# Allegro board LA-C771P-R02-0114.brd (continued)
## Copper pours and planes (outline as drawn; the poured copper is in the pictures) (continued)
+3VALW_EC on TOP (solid shape): 63.48,30.99 63.79,30.81 64.09,30.99 69.22,30.99 69.35,30.87 69.35,30.84 69.51,30.68 69.51,30.2 69.75,29.96 69.75,29.93 69.77,29.78 69.84,29.65 69.84,28.34 69.84,28.34 69.84,26.99 69.79,26.93 69.65,26.93 69.63,26.95 69.63,28.96 69.37,29.22 65.44,29.22 65.03,28.81 65.03,26.27 64.83,26.07 62.16,26.07 62.16,26.08 61.96,26.08 61.83,26.12 61.7,26.13 61.67,26.12 61.45,26.34 61.45,27.22 61.46,27.27 61.46,27.31 61.46,28.04 61.46,28.08 61.45,28.13 61.45,29.9 62.54,30.99
+3VALW_EC on TOP (solid shape): outline of 89 points within 53.02,1.31 81.59,32.55
+3VALW_EC on BOTTOM (solid shape): outline of 145 points within 53.37,28.61 63.91,33.61
+3VALWP on BOTTOM (solid shape): 204.3,40.19 204.3,35.54 201.89,33.13 200.14,33.13 199.96,33.31 199.96,34.27 199.65,34.58 199.16,34.58 197.61,36.13 197.61,39.94 196.81,40.75 196.81,42.09 197.06,42.35 202.14,42.35
+3VDD_CODEC on TOP (solid shape): 31.29,30.32 31.28,30.3 31.28,29.41 31.35,29.41 31.35,29.3 31.04,28.99 29.34,28.99 28.93,28.99 27.95,28 27.95,27.29 27.69,27.03 26.94,27.03 26.86,27.12 26.86,28.05 28.41,29.6 28.41,29.88 28.56,30.03 28.56,30.2 28.63,30.28 30.05,30.28 30.21,30.44 31.17,30.44
+3VLP on BOTTOM (solid shape): 189.44,42.12 189.44,41.57 189.68,41.33 189.87,41.33 190.59,40.61 190.59,39.96 190.53,39.9 190.37,39.9 190.34,39.94 190.34,40.48 190.06,40.76 189.42,40.76 189.01,41.18 187.99,41.18 187.86,41.31 187.86,42.25 187.94,42.32 189.24,42.32
+3VS on TOP (solid shape): 76.13,5.85 76.13,5.39 75.88,5.14 75.39,5.14 74.91,4.66 73.69,4.66 73.21,5.14 73.21,5.88 73.36,6.03 75.95,6.03
+3VS on TOP (solid shape): 79,76.18 79,75.39 78.97,75.37 78.97,74.78 78.8,74.6 77.98,74.6 77.86,74.73 77.86,76.15 77.96,76.26 78.92,76.26
+3VS on TOP (solid shape): 76.81,89.61 76.82,89.54 76.82,88.6 77.31,88.11 77.32,88.1 77.64,87.57 78.02,87.09 78.04,87.08 78.04,85.86 77.86,85.68 77.05,85.68 76.79,85.94 76.79,85.96 76.69,86.19 76.46,86.29 76.44,86.29 76.18,86.55 75.37,86.55 74.96,86.14 74.89,86.14 74.81,86.06 74.23,86.06 73.9,86.39 73.9,86.85 74.26,87.22 74.44,87.22 74.56,87.33 74.56,88.42 74.6,88.43 74.91,88.71 74.75,89.09 74.75,89.68 74.89,89.82 76.59,89.82
+3VS on TOP (solid shape): 177.02,86.85 177.02,86.14 177.01,86.13 177.01,85.39 176.82,85.2 173.31,85.2 172.79,85.72 172.76,85.82 172.84,85.9 173.07,86.4 172.54,86.52 172.43,86.51 172.37,86.6 172.37,86.84 172.52,87.13 172.37,87.42 172.37,87.89 172.63,88.15 175.72,88.15
+3VS on TOP (solid shape): outline of 501 points within 117.89,1.38 210.78,40.75
+3VS on TOP (solid shape): outline of 1002 points within 28.65,9.67 76.41,100.44
+3VS on BOTTOM (solid shape): 62.16,100.9 62.16,98.2 62.2,98.16 62.2,98.05 62,97.85 60.51,97.85 60.15,98.21 60.15,98.52 60.98,99.34 61,99.35 61.23,99.5 61.33,99.77 61.33,100.66 61.32,100.72 61.6,101 62.06,101
+3VS on IN1 (solid shape): 185.25,22.16 186.82,22.16 187.15,21.83 187.15,20.18 186.47,19.49 183.14,19.49 182.05,20.58 182.05,22.79 182.51,23.25 184.16,23.25
+3VS on IN1 (solid shape): 179.03,86.78 179.03,85.84 178.98,85.78 178.98,84.41 178.62,84.06 175.34,84.06 175.19,84.21 175.19,86.93 175.45,87.18 178.62,87.18
+3VS on IN2 (solid shape): outline of 619 points within 38.82,1.53 126.6,11.08
+3VS_CMOS on BOTTOM (solid shape): 55.35,94.87 55.35,92.72 55.76,92.31 56.55,92.31 56.72,92.13 56.72,91.27 56.57,91.11 54.46,91.11 54.31,91.27 54.31,94.98 54.36,95.03 55.2,95.03
+3VS_OUT on TOP (solid shape): 186.47,24.72 186.7,24.64 186.92,24.72 187.89,24.72 187.93,24.68 187.93,24.02 187.94,24.02 187.94,21.93 187.86,21.85 187.18,21.85 187.15,21.82 187.15,21.32 187.13,21.29 186.77,21.29 186.75,21.32 186.75,21.82 186.72,21.85 185.98,21.85 185.96,21.82 185.96,21.32 185.93,21.29 185.55,21.29 185.53,21.32 185.53,21.8 185.5,21.82 184.87,21.82 184.82,21.87 184.82,23.37 185.15,23.7 185.15,24.24 185.22,24.31 185.88,24.31 186.29,24.72
+3VS_TCM on TOP (solid shape): 93.71,20.3 93.71,19.18 93.48,18.95 90.43,18.95 90.38,19 90.38,19.46 90.51,19.59 90.51,20.45 90.56,20.5 93.5,20.5
+3VS_TCM on TOP (solid shape): 101.25,26.66 101.25,21.7 101.25,21.67 101.02,21.45 100.92,21.34 100.92,18.8 100.29,18.17 99.42,18.17 99.07,18.53 99.07,19.41 99.6,19.95 99.6,21.57 100.06,22.03 100.06,22.06 100.06,22.07 100.11,22.25 100.06,22.43 100.06,24.11 100.06,24.12 100.08,24.24 100.06,24.36 100.06,24.37 100.06,25.13 99.3,25.89 97.8,25.89 97.67,26.02 97.67,26.3 97.77,26.4 99.5,26.4 99.96,26.86 101.05,26.86
+3VS_TCM on BOTTOM (solid shape): 101,19.39 101,18.45 100.9,18.35 91.68,18.35 91.04,18.98 91.04,19.54 91.17,19.67 100.72,19.67
+3VS_WLAN on TOP (solid shape): 173.96,94.05 173.94,94.02 173.85,93.48 174.05,92.96 174.05,88.81 172.56,88.81 172.56,88.53 172.12,88.53 171.35,89.29 171.35,89.46 171.4,89.5 171.4,92.38 172.19,93.17 172.19,94.06 172.63,94.5 173.52,94.5
+3VS_WLAN on BOTTOM (solid shape): 154.87,92.8 154.87,90.74 154.08,89.95 153.17,89.95 153.02,90.1 153.02,90.38 153.4,90.76 153.4,92.8 153.53,92.92 154.74,92.92
+3VS_WLAN on IN1 (solid shape): 160.92,94.45 160.92,93.72 160.92,93.65 160.94,93.58 160.94,93.4 161.25,93.1 167.27,93.1 167.34,93.07 167.37,93 167.77,92.67 168.07,93.1 168.09,93.19 168.17,93.23 171.61,93.23 171.61,93.23 171.96,93.23 172.21,93.48 172.21,94.38 172.27,94.45 173.43,94.45 173.8,94.07 173.8,89.47 173.32,89 171.72,89 170.78,89.94 170.67,89.94 170.47,90.14 170.04,90.14 169.82,90.36 169.82,90.39 169.82,90.45 169.81,90.52 169.52,90.83 169.14,90.65 169.1,90.66 169.08,90.68 168.84,90.78 168.6,90.7 168.54,90.67 168.48,90.69 168.22,90.78 167.97,90.65 167.91,90.59 154.45,90.59 153.72,89.86 152.64,89.86 151.94,90.56 149.09,90.56 148.24,91.41 148.24,92.94 148.43,93.34 148.44,93.77 148.43,93.8 148.47,93.84 148.47,94.29 148.65,94.47 149.54,94.47 149.72,94.29 149.72,93.94 149.64,93.86 149.64,93.61 150.15,93.1 159.67,93.1 159.85,93.28 159.9,93.28 159.98,93.35 160.06,93.42 160.12,93.49 160.21,93.58 160.21,94.45 160.26,94.5 160.87,94.5
+5V_HUB on TOP (solid shape): 193.96,57.26 194.52,57.26 194.67,57.11 194.67,55.84 194.47,55.63 194.47,53.09 194.46,53.08 194.46,52.78 194.34,52.66 193.17,52.66 192.96,52.88 192.96,56.69 193.56,57.29 193.94,57.29
+5V_ODD on TOP (solid shape): 225.31,109.45 225.86,109.07 226.41,109.45 226.42,109.48 226.51,109.48 226.87,109.12 226.87,107.28 226.54,106.94 225.46,106.94 225.41,106.89 225.37,106.93 225.37,106.94 224.33,106.9 224.96,106.07 225.04,106.05 225.08,105.97 225.08,105.17 224.79,104.88 221.52,104.88 221.44,104.96 221.44,105.72 221.93,106.22 221.93,107.35 224.06,109.48 225.3,109.48
+5VALW on TOP (solid shape): 192.13,30.01 192.13,28.38 192.06,28.3 191.55,28.3 191.34,28.1 191.34,27.56 189.85,26.07 189.24,26.07 189.13,26.17 189.13,26.73 188.76,27.11 188.76,29.3 189.77,30.31 191.83,30.31
+5VALW on TOP (solid shape): 191.14,54.62 191.85,54.62 191.96,54.52 191.96,54.14 192.13,53.96 192.67,53.96 192.77,53.86 192.77,52.43 192.23,51.9 190.08,51.9 189.9,52.08 189.9,52.13 189.75,52.28 188.98,52.28 188.73,52.54 188.73,53.86 188.83,53.96 189.09,53.96 189.75,54.62 190.33,54.62 190.48,54.77 190.99,54.77
+5VALW on BOTTOM (solid shape): 36.74,49.74 36.74,37.37 40.37,33.73 41.95,33.73 41.96,33.74 43.52,33.74 43.57,33.69 43.57,33.23 43.59,33.21 45.55,33.21 45.58,33.23 45.58,33.69 45.63,33.74 47.4,33.74 47.41,33.74 47.55,33.74 47.68,33.61 47.68,31.35 47.61,31.27 39.07,31.27 33.6,36.75 33.6,36.84 32.8,37.64 32.8,39.66 32.7,39.66 32.06,40.29 17.94,40.29 17.48,40.75 17.48,42.27 17.58,42.38 18.7,42.38 19.06,42.02 22,42.02 23.43,43.44 28.86,43.44 35.57,50.15 36.33,50.15
+5VALW on IN1 (solid shape): outline of 115 points within 182.94,27.31 193.12,54.77
+5VALW on IN1 (solid shape): outline of 2550 points within 40.72,5.11 181.66,33.99
+5VALW on IN2 (solid shape): outline of 1216 points within 173.31,8.52 195,30.18
+5VALWP on BOTTOM (solid shape): 48.98,41.03 48.98,37.08 48.96,37.06 48.96,35.34 47.53,33.91 41.92,33.91 39.68,36.15 39.68,37.72 39.83,37.87 41.32,37.87 41.51,38.06 41.51,38.88 43.11,40.47 46.21,40.47 47.02,41.28 48.72,41.28
+5VS on TOP (solid shape): 225.17,103.73 225.17,100.84 224.81,100.49 223.14,100.49 222.6,101.03 222.6,101.75 221.3,103.05 221.3,104.01 221.43,104.15 224.76,104.15
+5VS on TOP (solid shape): 33.57,25.85 34.08,25.85 35.24,24.7 35.24,14.46 36.36,13.34 36.36,13.24 36.71,12.89 36.71,11.52 36.25,11.06 35.62,11.06 33.89,12.79 33.89,23.58 32.72,24.75 31.5,24.75 31.43,24.82 31.43,25.76 31.53,25.87 33.56,25.87
+5VS on TOP (solid shape): 18.18,15.41 18.18,15.23 18.18,15.23 18.08,14.35 18.18,13.47 18.18,13.47 18.18,12.87 17.97,12.66 17.2,12.66 17,12.86 17,15.5 17.08,15.58 18.02,15.58
+5VS on TOP (solid shape): 21.01,89.77 21.01,88.65 20.86,88.5 16.87,88.5 16.66,88.71 16.66,88.74 16.64,88.95 16.49,89.11 16.49,89.67 16.76,89.94 18.28,89.94 18.34,90 18.42,90.03 18.49,89.99 18.83,89.88 19.09,90.12 19.1,90.15 20.63,90.15
+5VS on TOP (solid shape): outline of 202 points within 180.12,29.24 210.42,52.1
+5VS on BOTTOM (solid shape): outline of 571 points within 180.35,5.62 194.85,32.09
+5VS on IN1 (solid shape): 22.08,89.85 22.08,88.71 21.72,88.35 20.2,88.35 19.74,88.81 19.74,89.72 20.28,90.26 21.67,90.26
+5VS on IN1 (solid shape): 225.21,103.4 225.21,98.65 225.01,98.46 222.91,98.46 222.62,98.74 222.62,102.98 223.4,103.76 224.84,103.76
+5VS on IN1 (solid shape): 188.12,30.74 188.12,29.3 188.11,29.28 188.11,28.77 187.82,28.48 182.94,28.48 181.95,29.47 181.95,32.24 182.38,32.67 186.19,32.67
+5VS on IN1 (solid shape): outline of 372 points within 103.21,1.3 193.06,10.7
+5VS on IN1 (solid shape): outline of 1094 points within 17.1,1.41 79.69,15.76
+5VS_HDD on TOP (solid shape): 211,55.08 211.69,55.08 211.75,55.01 212.29,55.01 212.4,54.89 212.4,51.59 212.27,51.47 211.13,51.47 210.22,52.38 207.81,52.38 207.68,52.51 207.68,54.54 207.92,54.78 207.92,55.11 207.93,55.13 207.93,55.86 208.14,56.07 210.01,56.07
+5VS_OUT on TOP (solid shape): 188.27,29.06 188.27,27.16 187.86,26.75 187.86,26.09 187.84,26.07 186.77,26.07 186.24,26.6 185.45,26.6 185.45,26.6 185.22,26.6 185.15,26.68 185.15,29.04 185.22,29.11 188.22,29.11
+5VS_PVDD on TOP (solid shape): 30.97,27.18 30.97,25.68 30.9,25.68 30.9,24.79 30.92,24.79 30.96,24.76 30.95,24.7 30.89,24.65 30.11,24.65 30.03,24.72 30.03,24.97 30.03,24.97 30.03,25.59 30.03,25.68 29.83,25.89 28.94,25.89 28.81,26.01 28.81,27.16 29.09,27.44 30.71,27.44
+5VS_PVDD on BOTTOM (solid shape): 30,27.64 30,27.01 29.75,26.75 29.24,26.75 29.22,26.78 29.06,26.78 28.56,26.27 27.84,26.27 27.84,28.22 27.88,28.25 27.92,28.28 29.37,28.28
+12.6VB_DDR on TOP (solid shape): 142.95,31.41 142.95,28.77 143.13,28.59 143.13,26.3 143.32,26.11 143.32,26.04 143.19,25.92 143.13,25.92 142.94,26.11 141.99,26.11 141.86,26.23 141.86,26.61 141.61,26.87 140.91,26.87 140.46,27.31 140.46,31.25 140.78,31.57 142.8,31.57
+12.6VB_DDR on BOTTOM (solid shape): 143,28.77 143,26.3 142.81,26.11 141.99,26.11 141.99,26.61 141.73,26.87 139.75,26.87 139.51,27.11 139.51,28.14 139.57,28.2 140.78,28.2 141.16,28.58 141.16,28.77 141.29,28.9 142.88,28.9
+AV12 on TOP (solid shape): 45.73,15.2 45.78,15.13 45.91,15.02 45.91,14.61 45.86,14.57 43.93,14.57 43.54,14.18 43.54,13.98 43.47,13.9 42.93,13.9 42.83,14 42.83,15.83 42.88,15.88 45.04,15.88
+V18R on TOP (solid shape): 83.11,26.17 83.11,25.43 82.96,25.28 82.12,25.28 81.4,24.55 81.22,24.55 81.11,24.45 81.11,24.44 78.9,24.44 78.85,24.49 78.85,24.62 78.92,24.69 80.73,24.69 80.76,24.72 80.78,24.72 81.7,25.64 81.75,25.72 81.77,25.82 81.77,25.84 82.28,26.34 82.94,26.34
+VCC_LPC on TOP (solid shape): 75.88,31 76.1,31 76.19,30.9 76.19,30.23 76.2,30.16 76.23,30.08 76.23,29.92 75.22,28.91 74.84,28.91 73.74,30.01 73.74,30.87 73.87,31 75.88,31
+VCC_SPI on TOP (solid shape): 82.9,28.93 82.9,26.58 82.84,26.52 82.04,26.52 81.69,26.17 81.69,25.94 81.62,25.86 81.62,25.81 81.49,25.69 81.24,25.69 81.24,28.72 81.48,28.97 82.87,28.97
GND on TOP (solid shape): 28.94,44.03 28.94,40.32 26.98,38.36 25.05,38.36 24.26,39.15 24.26,44.18 24.32,44.23 28.74,44.23
GND on TOP (solid shape): 34.75,63.43 34.75,61.5 34.55,61.3 33.26,61.3 32.57,61.98 32.57,63.43 32.77,63.63 34.56,63.63
GND on TOP (solid shape): 65.43,74.49 65.43,72.96 65.24,72.77 64.45,72.77 63.74,73.48 63.74,74.13 64.29,74.68 65.24,74.68
GND on TOP (solid shape): 92.34,92.57 92.34,89.37 92.16,89.19 89.75,89.19 89.7,89.24 89.7,92.82 89.75,92.87 92.03,92.87
GND on TOP (solid shape): 147.12,65.82 147.12,62.16 146.75,61.8 143.92,61.8 143.74,61.98 143.74,65.79 143.91,65.96 146.98,65.96
GND on TOP (solid shape): 157.3,63.33 157.3,60.63 157.07,60.4 154.57,60.4 154.36,60.62 154.36,63.3 154.58,63.52 157.12,63.52
GND on TOP (solid shape): 199.11,69.1 199.11,68.27 198.98,68.14 197.2,68.14 197.07,68.27 197.07,69.1 197.2,69.22 198.98,69.22
GND on TOP (solid shape): 199.12,79.69 199.12,78.42 198.99,78.29 197.59,78.29 197.54,78.34 197.54,79.61 197.72,79.79 199.02,79.79
GND on TOP (solid shape): 60.94,64.17 60.94,63.12 60.84,63.02 59.49,63.02 59.26,62.79 56.24,62.79 55.96,63.07 55.96,64.22 56.09,64.34 60.76,64.34
GND on TOP (solid shape): 37.19,70.03 37.19,68.72 36.74,68.26 36.74,67.67 35.88,66.81 34.68,66.81 34.07,67.41 34.07,69.68 34.88,70.49 36.74,70.49
GND on TOP (solid shape): 68.24,72.33 68.24,70.71 68.23,70.69 66.49,70.69 66.13,71.06 66.13,71.44 66.19,71.5 66.57,71.5 67.08,72.01 67.08,72.33 67.14,72.39 68.18,72.39
GND on TOP (solid shape): 154.61,32.27 154.88,32.27 154.94,32.2 154.94,30.8 154.88,30.74 152.76,30.74 152.48,31.02 152.48,32.26 152.58,32.36 154.52,32.36
GND on TOP (solid shape): 70.81,83.41 70.85,83.41 71.54,82.72 71.54,80.18 71.43,80.07 69.63,80.07 69.36,80.33 69.36,83.33 69.53,83.5 70.72,83.5
GND on TOP (solid shape): 111.82,97.98 111.82,95.18 111.81,95.17 111.81,94.76 111.72,94.67 107.7,94.67 107.63,94.75 107.63,95.79 107.7,95.87 107.7,96.17 108.06,96.53 108.06,97.98 108.24,98.15 111.64,98.15
GND on TOP (solid shape): 141.36,71.28 141.36,69.02 141.08,68.74 140.37,68.74 139.63,69.48 135.8,69.48 135.36,69.05 135.01,69.05 134.53,69.53 134.53,70.62 134.73,70.82 139.66,70.82 140.34,71.51 141.13,71.51
GND on TOP (solid shape): 166.18,73.08 166.18,69.05 165.84,68.72 153.9,68.72 153.65,68.97 153.65,72.42 154.08,72.85 157.49,72.85 158.19,72.14 161.15,72.14 161.63,72.63 161.63,73.41 161.88,73.67 165.59,73.67
GND on TOP (solid shape): 59.62,61.57 59.62,59.85 59.57,59.8 58.98,59.8 58.86,59.92 58.86,60.41 58.8,60.47 58.8,60.53 58.74,60.53 58.71,60.56 58.15,60.56 57.97,60.74 57.97,61.65 58.05,61.73 59.47,61.73
GND on TOP (solid shape): 201.39,72.08 203.23,72.08 203.23,71.45 202.79,71.45 202.53,71.19 202.53,69.99 202.22,69.67 199.55,69.67 199.36,69.86 199.36,71.7 199.49,71.83 200.06,71.83 200.19,71.95 200.19,72.46 200.25,72.53 200.95,72.53
GND on TOP (solid shape): 44.61,98.59 44.61,96.91 43.14,95.44 40.72,95.44 39.89,94.6 39.88,94.6 39.56,94.27 33.77,94.27 33.62,94.42 33.62,97.26 34.04,97.68 36.12,97.68 36.22,97.79 36.33,97.79 37.39,98.84 44.36,98.84
GND on TOP (solid shape): 86.8,84.03 86.8,83.42 86.49,83.12 85.55,83.12 85.38,82.94 85.38,81.67 85.3,81.59 84.34,81.59 84.18,81.75 84.18,83.14 84.26,83.22 84.79,83.22 84.89,83.32 84.89,83.32 85.83,84.26 86.57,84.26
GND on TOP (solid shape): 192.83,56.33 192.83,54.25 192.72,54.14 192.23,54.14 192.08,54.29 192.08,54.57 192.08,54.67 191.93,54.82 191.27,54.82 191.07,55.03 191.07,55.59 191.23,55.75 191.23,55.88 191.78,56.42 192.21,56.42 192.74,56.42
GND on TOP (solid shape): 209.41,47.94 209.41,47.3 209.35,47.25 208.69,47.25 208.67,47.23 208.49,47.23 208.16,46.9 208.16,41.77 207.81,41.41 206.47,41.41 206,41.88 206,47.48 206.54,48.01 209.33,48.01
GND on TOP (solid shape): 147.13,28.77 147.13,27.95 147.32,27.76 147.89,27.76 148.08,27.57 149.54,27.57 149.61,27.5 149.61,26.49 149.23,26.11 143.7,26.11 143.64,26.17 143.64,27.83 143.97,28.16 144.74,28.16 145.48,28.9 147,28.9
GND on TOP (solid shape): 143.3,86.62 143.3,83.5 142.14,82.35 139.43,82.35 137.98,80.91 133.64,80.91 133.51,81.03 133.51,82.11 133.7,82.3 136.16,82.3 136.18,82.33 136.31,82.33 136.96,82.99 138.11,82.99 138.69,83.57 138.69,84.41 139.48,85.2 139.81,85.2 141.61,87 142.91,87
GND on TOP (solid shape): 147.95,79.27 147.95,74.85 147.6,74.5 134.2,74.5 133.76,74.94 133.76,75.77 134.17,76.18 138.36,76.18 138.99,75.54 142.93,75.54 142.94,75.56 144.16,75.56 145.07,76.47 145.07,79.22 145.23,79.38 147.83,79.38
GND on TOP (solid shape): 185.26,66.68 190.47,66.68 190.62,66.53 190.62,65.57 190.77,65.41 192.12,65.41 192.31,65.6 192.31,66.37 192.5,66.56 193.33,66.56 193.33,65.22 192.88,64.78 185.45,64.78 184.37,65.86 184.37,66.81 184.44,66.87 185.07,66.87
GND on TOP (solid shape): 63.35,61.63 63.35,60.84 63.46,60.74 63.99,60.74 64.06,60.66 64.06,59.85 63.86,59.64 62.64,59.64 62.24,59.24 61.83,59.24 61.78,59.29 61.78,60.15 61.63,60.3 60.41,60.3 60.36,60.36 60.36,61.22 60.38,61.24 62.26,61.24 62.31,61.3 62.31,61.57 62.46,61.73 63.25,61.73
GND on TOP (solid shape): 95.66,95.87 95.66,94.62 95.59,94.55 94.72,94.55 94.47,94.8 94.47,95.26 94.29,95.44 94.29,95.51 94.22,95.51 94.19,95.54 94.17,95.55 93.88,95.64 93.58,95.54 93.56,95.54 93.48,95.61 93.48,96.4 93.78,96.71 94.83,96.71
GND on TOP (solid shape): 113.83,74.86 113.83,73.92 114.23,73.51 114.23,72.9 114.12,72.79 114.12,71.55 114.15,71.51 114.15,70.8 114.08,70.72 113.47,70.72 113.42,70.77 113.42,71.56 113.35,71.64 113.35,72.68 113.06,72.97 112.77,72.97 112.58,73.16 112.58,73.41 112.66,73.49 112.94,73.49 112.96,73.52 112.99,73.52 112.99,73.54 113.06,73.62 113.06,74.13 112.99,74.2 112.99,74.28 112.91,74.28 112.83,74.35 112.56,74.35 112.48,74.43 112.48,74.94 112.58,75.04 113.65,75.04
GND on TOP (solid shape): 111.86,78.77 112.43,78.77 112.44,78.78 112.57,78.78 112.58,78.77 112.58,78.18 112.44,78.04 112.44,78.02 112.38,77.96 112.38,77.55 112.43,77.5 112.43,76.76 112.38,76.71 112.38,75.41 112.29,75.32 111.82,75.32 111.68,75.47 111.68,75.57 111.54,75.71 111.54,75.77 111.48,75.77 111.37,75.88 111.08,75.88 110.89,76.08 110.89,76.62 111.29,76.62 111.54,76.87 111.54,77.94 111.28,78.2 110.85,78.2 110.8,78.25 110.8,78.9 110.85,78.95 111.68,78.95
GND on TOP (solid shape): 111.36,74.25 111.36,73.79 111.59,73.56 111.59,73 111.77,72.83 112.09,72.83 112.38,72.54 112.38,71.63 112.32,71.58 110.07,71.58 109.99,71.62 109.97,71.71 109.94,71.95 109.75,72.2 109.81,72.2 109.81,72.85 110.78,72.85 110.9,72.98 110.9,73.46 110.52,73.84 110.52,74.4 110.57,74.45 111.16,74.45
GND on TOP (solid shape): 109.28,82.3 109.28,81.46 109.43,81.31 109.54,81.31 109.54,81.31 109.67,81.28 109.79,81.31 109.8,81.31 109.84,81.31 109.91,81.23 109.91,80.36 109.89,80.34 109.89,79.81 109.84,79.76 109.3,79.76 109.23,79.84 109.23,80.24 109.23,80.5 109.07,80.65 107.15,80.65 106.89,80.91 106.89,81.08 106.74,81.23 106.18,81.23 106.05,81.36 106.05,82.02 106.08,82.05 106.79,82.05 106.86,81.97 106.86,81.74 106.98,81.63 107.68,81.63 107.92,81.87 107.92,82.32 108.03,82.43 108.54,82.43 108.74,82.63 108.95,82.63
GND on TOP (solid shape): 13.93,26.95 13.93,25.72 12.1,23.89 1.47,23.89 1.46,25.5 1.46,25.64 1.48,25.71 1.55,25.79 1.61,25.83 1.62,25.83 1.66,25.84 9.18,25.84 9.19,25.83 9.22,25.78 9.26,25.7 9.28,25.67 9.32,25.62 9.34,25.59 9.39,25.54 9.42,25.52 9.47,25.48 9.55,25.43 9.61,25.4 9.64,25.39 9.74,25.36 9.8,25.35 9.91,25.34 10.03,25.35 10.16,25.39 10.31,25.46 10.39,25.52 10.46,25.59 10.54,25.69 10.57,25.75 10.62,25.87 10.65,25.98 10.66,26.05 10.66,26.09 10.66,27.13 10.9,27.37 13.52,27.37
GND on TOP (solid shape): 105.65,78.97 105.73,78.97 106.16,78.55 106.16,78.53 106.63,78.28 106.73,78.8 106.71,78.91 106.81,78.97 109.66,78.97 109.88,78.74 109.88,78.44 109.69,78.25 107.77,78.25 107.64,78.12 107.64,77.85 107.39,77.61 106.33,77.61 105.64,78.29 105.24,78.29 105.15,78.37 105.15,78.85 105.28,78.97 105.65,78.97
GND on TOP (solid shape): 154.66,80.62 157.11,80.62 157.22,80.51 157.22,80.18 156.97,79.93 156.97,79.46 157.13,79.3 158.1,79.3 158.23,79.17 158.23,76.78 158.06,76.62 156.19,76.62 156.06,76.75 156.06,77.6 155.92,77.74 155.92,77.75 155.86,77.83 155.78,77.89 155.77,77.89 155.67,77.99 154.82,77.99 154.65,77.82 154.65,76.96 154.6,76.91 154.03,76.91 153.98,76.96 153.98,77.87 153.56,78.29 153.25,78.29 153,78.04 153,76.88 152.87,76.75 152.63,76.75 152.61,76.74 152.48,76.74 152.46,76.75 151.98,76.75 151.95,76.74 151.78,76.74 151.76,76.75 151.29,76.75 151.27,76.74 151.09,76.74 151.07,76.75 150.72,76.75 150.59,76.88 150.59,78.46 150.45,78.6 149.58,78.6 149.48,78.7 149.48,80.15 149.55,80.23 150.85,80.23 151.43,80.81 154.47,80.81
GND on TOP (solid shape): 107.98,87.13 107.98,85.37 107.97,85.36 107.97,84.4 107.65,84.08 107.65,82.66 106.7,82.66 106.68,82.67 106.63,82.69 106.58,82.71 106.52,82.71 106.47,82.71 106.42,82.7 106.37,82.68 106.33,82.66 106.23,82.66 106.03,82.86 106.03,84.66 105.95,84.74 106.38,84.74 106.38,84.69 106.39,84.64 106.41,84.59 106.43,84.54 106.46,84.5 106.5,84.46 106.54,84.43 106.58,84.41 106.63,84.39 106.69,84.38 106.74,84.38 106.79,84.39 106.84,84.41 106.88,84.43 106.93,84.46 106.96,84.5 106.99,84.54 107.02,84.59 107.03,84.64 107.04,84.69 107.04,84.74 107.03,84.79 107.02,84.84 106.99,84.89 106.96,84.93 106.93,84.97 106.88,85 106.84,85.02 106.79,85.04 106.74,85.04 106.69,85.04 106.63,85.04 106.58,85.02 106.54,85 106.5,84.97 106.46,84.93 106.43,84.89 106.41,84.84 106.39,84.79 106.38,84.74 105.95,84.74 105.75,84.94 105.75,87.66 105.95,87.86 107.24,87.86
GND on TOP (solid shape): 17.31,48.65 17.31,41.69 14.23,38.62 12.15,38.62 12.14,38.61 10.85,38.61 10.66,38.81 10.66,39.75 10.65,39.75 10,40.45 9.19,39.95 2.8,39.95 2.63,40.03 2.55,40.2 2.55,44.6 2.63,44.77 2.8,44.85 11.5,44.85 12.3,44.05 13.05,44.8 13.05,44.96 13.08,44.98 13.08,46.81 13.22,46.95 14.61,46.95 14.64,46.92 14.82,47.1 14.82,48.95 15.04,49.18 16.77,49.18
GND on TOP (solid shape): 105.11,79.81 105.11,79.23 104.98,79.1 104.27,79.1 104.2,79.18 104.08,79.18 103.92,79.33 103.84,79.25 103.68,79.25 103.02,78.59 103.02,76.63 103.02,76.62 102.98,76.51 102.99,76.4 102.99,76.37 102.83,76.21 102.44,76.21 102.38,76.27 101.64,76.27 101.64,76.59 100.88,76.59 100.88,76.27 100.67,76.06 100.49,76.06 100.16,76.38 100.16,76.7 101.04,77.58 101.66,77.58 102.16,78.09 102.16,78.13 102.29,78.46 102.05,78.72 102.03,78.72 101.88,78.87 101.88,78.89 101.81,78.99 101.71,79.06 101.7,79.06 101.66,79.1 101.66,79.28 101.66,79.29 101.68,79.4 101.66,79.5 101.66,79.51 101.66,79.63 101.73,79.71 102.02,79.71 102.21,79.52 102.2,79.49 102.42,79.11 102.82,79.27 102.83,79.28 102.87,79.32 102.88,79.38 102.88,79.45 103.38,79.96 104.97,79.96
GND on TOP (solid shape): 6.31,7.17 10.15,6.93 12,3.55 11.54,1.69 10.27,0.25 9.11,0.25 9.11,0.25 6.57,0.72 4.32,1.98 4.32,1.99 4,3.62 4.38,5.25
GND on TOP (solid shape): outline of 128 points within 1.45,94.24 147.01,102.2
GND on TOP (solid shape): outline of 320 points within 1.45,76.95 17.23,88.22
GND on TOP (solid shape): outline of 180 points within 110.34,70.31 119.59,85.17
GND on TOP (solid shape): outline of 4000 points within 1.48,0.25 228.15,115.65
GND on BOTTOM (solid shape): 207.35,44.01 203.35,44.01 203.35,64.01 207.35,64.01
GND on BOTTOM (solid shape): 213.89,93.46 209.89,93.46 209.89,105.46 213.89,105.46
GND on BOTTOM (solid shape): 221.1,81.55 211.1,81.55 211.1,91.55 221.1,91.55
GND on BOTTOM (solid shape): 187.83,36.79 186.82,36.79 186.69,36.91 186.69,38.12 186.88,38.31 187.83,38.31
GND on BOTTOM (solid shape): 138.31,82.2 138.31,80.95 138.16,80.8 133.59,80.8 133.59,82.38 133.74,82.53 137.98,82.53
GND on BOTTOM (solid shape): 44.56,51.39 44.56,50.25 43.04,50.25 43.04,51.27 43.26,51.49 44.46,51.49
GND on BOTTOM (solid shape): 53.98,101.02 53.98,97.85 53.85,97.72 52.13,97.72 52,97.85 52,101.1 52.03,101.12 53.88,101.12
GND on BOTTOM (solid shape): 57.56,83.32 57.56,81.21 57.36,81.01 56.04,81.01 55.94,81.11 55.94,82.65 56.81,83.52 57.36,83.52
GND on BOTTOM (solid shape): 139.96,76.05 139.96,74.88 139.71,74.63 133.89,74.63 133.59,74.94 133.59,76.05 133.79,76.26 139.76,76.26
GND on BOTTOM (solid shape): 199.01,78.37 197.68,78.37 197.55,78.49 197.55,79.64 197.68,79.76 199.01,79.76
GND on BOTTOM (solid shape): 201.28,44.26 201.28,42.91 201.12,42.76 197.01,42.76 196.78,42.99 196.78,44.26 197.26,44.74 200.79,44.74
GND on BOTTOM (solid shape): 131.58,83.09 131.58,78.8 131.5,78.72 130.59,78.72 130.35,78.96 130.36,78.98 130.36,83.25 130.39,83.27 131.4,83.27
GND on BOTTOM (solid shape): 199.73,34.03 199.73,32.73 199.52,32.52 198.65,32.52 198.5,32.67 198.5,34.04 198.66,34.2 199.56,34.2
GND on BOTTOM (solid shape): 148.19,27.51 148.37,27.51 148.7,27.18 148.7,26.27 148.49,26.07 143.72,26.07 143.64,26.14 143.64,27.84 143.8,28 147.71,28
GND on BOTTOM (solid shape): 158.28,79.17 158.28,77.3 158.17,77.19 156.88,77.19 156.75,77.32 156.75,79.15 156.89,79.28 158.17,79.28
GND on BOTTOM (solid shape): 188.12,65.44 192.57,65.44 192.74,65.26 192.74,64.42 192.51,64.19 184.84,64.19 184.28,64.75 184.28,66.89 184.34,66.94 186.62,66.94
GND on BOTTOM (solid shape): 149.99,41.6 149.99,40.61 149.91,40.53 142.34,40.53 142.04,40.84 142.04,41.73 142.22,41.9 149.68,41.9
GND on BOTTOM (solid shape): 40.91,39.32 40.91,38.27 40.8,38.16 39.43,38.16 39.22,38.36 39.22,39.25 39.41,39.44 39.59,39.44 39.61,39.46 40.77,39.46
GND on BOTTOM (solid shape): 71.89,99.65 71.89,97.64 71.68,97.44 68.48,97.44 68.28,97.64 68.28,98.38 68.54,98.64 69.55,98.64 69.93,99.02 69.93,99.73 70.01,99.8 71.74,99.8
GND on BOTTOM (solid shape): 162.44,72.09 162.44,70.11 161.91,69.58 158.73,69.58 158.07,70.24 158.07,71.94 158.34,72.21 161.16,72.21 161.22,72.27 162.27,72.27
GND on BOTTOM (solid shape): 51.16,40.95 51.16,37.04 50.71,36.58 49.69,36.58 49.48,36.79 49.48,40.7 49.48,40.7 49.48,41.08 49.64,41.23 50.88,41.23
GND on BOTTOM (solid shape): 153.8,33.41 153.8,32.46 153.93,32.33 154.5,32.33 154.56,32.27 154.56,30.68 154.5,30.61 152.78,30.61 152.78,32.33 153.42,32.33 153.54,32.46 153.54,33.41 153.61,33.47 153.74,33.47
GND on BOTTOM (solid shape): 198.78,69.81 198.78,69.47 197.47,68.16 197.18,68.16 197.07,68.26 197.07,69.1 197.18,69.2 197.61,69.2 197.89,69.48 197.89,69.81 197.96,69.88 198.7,69.88
GND on BOTTOM (solid shape): 141.31,71.38 141.31,69.02 141.23,68.94 140.65,68.94 140.57,69.02 140.18,69.02 139.5,69.7 139.48,69.7 139.4,69.78 136.1,69.78 135.72,69.4 134.7,69.4 134.48,69.63 134.48,70.64 134.68,70.85 139.66,70.85 140.29,71.48 141.2,71.48
GND on BOTTOM (solid shape): 29.18,59.65 29.18,58.55 28.84,58.2 28.84,53.83 26.27,51.27 20,51.27 16.62,54.64 16.62,56.22 15.86,56.98 14.36,56.98 13.93,57.41 13.93,58.78 14.1,58.96 22.11,58.96 22.92,59.78 24.67,59.78 24.69,59.79 29.04,59.79
GND on BOTTOM (solid shape): 153.61,37.22 153.61,34.55 153.48,34.42 153.16,34.42 152.97,34.23 152.97,32.6 152.94,32.56 152.82,32.56 152.76,32.61 152.76,33.39 152.74,33.42 152.74,33.58 152.66,33.66 152.66,34.17 152.28,34.55 152.28,37.22 152.4,37.35 153.48,37.35
GND on BOTTOM (solid shape): 49.36,22.41 49.23,22.28 48.09,22.28 48.04,22.23 36.86,22.23 35.21,20.58 35.21,20.01 35.15,19.86 35.13,19.7 35.13,19.23 34.58,18.68 32.98,18.68 32.93,18.73 32.93,21.73 34.45,23.25 47.18,23.25 47.25,23.33 49.36,23.33
GND on BOTTOM (solid shape): 153.38,30.31 153.38,29.43 153.42,29.39 153.42,29 153.4,28.98 153.4,28.74 152.99,28.33 152.74,28.33 152.61,28.45 152.61,28.76 152.82,28.97 152.82,29.17 153.16,29.51 153.16,30.31 153.2,30.35 153.34,30.35
GND on BOTTOM (solid shape): 43.14,47.36 45.78,47.36 45.79,47.34 45.79,45.44 45.57,45.44 45.57,46.71 43.94,46.71 43.94,45.41 43.57,45.05 42.34,45.05 41.77,44.47 40.88,44.47 40.37,44.98 39.61,44.98 39.48,45.11 39.48,47.78 39.67,47.97 42.53,47.97
GND on BOTTOM (solid shape): 192.85,39.62 192.85,39.49 192.77,39.42 191.5,39.42 191.5,37.78 192.72,37.78 193.1,37.4 193.1,36.25 193.93,35.43 193.93,34.98 193.55,34.6 193.04,34.6 192.79,34.35 192.79,33.3 192.64,33.15 190.18,33.15 189.92,33.41 189.92,36.23 189.99,36.3 189.99,36.3 190.86,37.17 190.86,39.66 190.88,39.68 192.79,39.68
GND on BOTTOM (solid shape): 154.35,89.35 154.68,88.87 155.01,89.35 155.16,89.35 155.61,88.91 155.61,86.88 154.73,86 150.93,86 150.59,86.34 150.59,89.16 150.78,89.35
GND on BOTTOM (solid shape): 110.3,78.22 110.32,78.2 110.36,78.2 110.36,78.11 110.32,78.1 110.25,78.06 110.18,78.01 109.9,78.01 109.66,78.11 109.42,78.01 109.13,78.01 108.85,78.17 108.57,78.01 108.47,78.01 108.29,78.19 108.29,78.32 108.53,78.56 109.32,78.56 109.55,78.79 109.73,78.79
GND on BOTTOM (solid shape): 128.15,71.61 128.15,71 127.67,70.52 127.24,70.52 127.17,70.46 126.99,70.46 126.99,70.28 126.91,70.19 126.91,69.64 126.79,69.52 126.69,69.17 126.93,68.89 126.94,68.89 127.11,68.72 127.11,68.44 126.78,68.11 126.78,62.24 126.58,62.04 125.53,62.04 125.41,62.16 125.41,66.53 125.59,66.71 125.59,70.04 125.31,70.32 125.31,70.8 125.93,71.42 125.97,71.42 126.25,71.5 126.42,71.73 126.44,71.76 128,71.76
GND on BOTTOM (solid shape): 98.01,65.88 98.08,65.85 98.11,65.79 98.22,65.58 98.44,65.51 98.72,65.23 98.79,65.01 98.99,64.91 99.06,64.87 99.08,64.8 99.08,64.57 98.93,64.42 98.76,64.42 98.73,64.4 98.46,64.4 98.44,64.38 98.33,64.38 98.03,64.07 97.58,64.07 97.45,64.21 97.45,64.71 97.52,64.78 97.52,65.6 97.57,65.65 97.61,65.69 97.63,65.75 97.75,65.88
GND on BOTTOM (solid shape): 99.65,90.75 99.65,90.09 99.59,90.03 98.74,90.03 98.57,89.86 98.57,89.46 98.54,89.39 98.47,89.36 98.2,89.26 98.15,88.99 98.19,88.92 98.24,88.86 98.28,88.79 98.26,88.71 98.15,88.53 98.19,88.33 98.22,88.3 98.25,88.27 98.29,88.2 98.27,88.12 98.2,88.06 98.16,87.98 98.16,87.96 98.04,87.84 98.04,87.79 97.93,87.68 97.71,87.68 97.57,87.82 97.57,87.97 97.02,88.52 97.02,90.54 97.35,90.88 99.52,90.88
GND on BOTTOM (solid shape): 14.41,80.5 15.2,80.5 15.51,80.18 17.11,80.18 17.48,79.82 17.48,78.95 17.2,78.67 9.1,78.67 8.51,79.27 5.69,79.27 4.6,78.18 4.6,76.95 2.64,76.95 2.47,77.03 2.39,77.2 2.39,78.15 1.7,78.15 1.53,78.23 1.45,78.4 1.45,80.53 1.53,80.7 1.7,80.78 10.3,80.78 11.03,81.33 10.67,82.18 10.58,82.27 10.55,82.4 10.55,83.45 11.46,83.45
GND on BOTTOM (solid shape): 123.43,65.57 123.43,62.39 122.84,61.81 122.84,60.21 123.15,59.9 126.75,59.9 127.16,59.5 127.16,58.4 126.98,58.23 124.04,58.23 123.3,57.49 119.39,57.49 119.08,57.79 119.08,60.71 119.21,60.84 120.28,60.84 120.28,60.03 120.35,59.95 122,59.95 122.03,59.98 122.03,62.47 123.15,63.59 123.15,64.02 123.1,64.07 123.08,64.1 123.04,64.14 123,64.17 122.97,64.19 122.92,64.25 122.44,64.25 121.98,63.79 121.06,63.79 120.56,63.28 120.56,61.12 120.28,60.84 119.21,60.84 119.31,60.94 119.84,60.94 119.97,61.07 119.97,62.72 119.31,63.38 119.31,64.65 119.54,64.88 120.2,64.88 120.25,64.93 120.3,64.93 120.34,64.94 120.39,64.95 120.43,64.97 120.46,65 120.5,65.03 120.52,65.07 120.54,65.11 120.56,65.15 120.56,65.2 120.56,65.24 120.76,65.44 120.89,65.44 121.02,65.57 121.04,65.59 121.08,65.61 121.11,65.65 121.14,65.69 121.16,65.73 121.17,65.78 121.17,65.83 121.16,65.87 121.15,65.92 121.13,65.96 121.11,65.98 121.11,66.27 121.13,66.3 121.14,66.35 121.15,66.39 121.15,66.44 121.14,66.48 121.32,66.66 122.33,66.66
GND on BOTTOM (solid shape): 122.35,90.65 122.35,88.5 121.98,88.14 121.5,88.14 121.47,88.11 121.38,88.11 121.12,88.36 121.14,88.39 121.13,88.59 121.01,88.73 121,88.74 120.96,88.78 121,88.82 121.01,88.83 121.11,89.25 120.67,89.26 120.59,89.23 120.52,89.27 120.49,89.29 120.47,89.32 120.43,89.39 120.46,89.47 120.29,89.97 120.08,89.49 120.05,89.4 119.94,89.4 119.93,89.41 119.8,89.47 119.66,89.46 119.63,89.46 119.37,89.72 119.35,89.79 119.35,90.33 120.67,91.65 121.34,91.65
GND on BOTTOM (solid shape): 120.13,76.9 120.14,76.89 120.19,76.8 120.28,76.74 120.29,76.74 120.33,76.7 120.38,76.7 120.46,76.66 120.47,76.57 120.46,76.52 120.46,76.46 120.46,76.43 120.47,76.39 120.46,76.3 120.38,76.26 120.35,76.26 120.11,75.99 120.35,75.72 120.43,75.73 120.5,75.66 120.68,75.66 120.72,75.62 120.77,75.62 120.89,75.49 121.25,75.49 121.46,75.7 121.94,75.7 122.02,75.77 122.12,75.78 122.3,75.59 122.3,75.08 122.04,74.82 121.41,74.82 121.37,74.83 121.33,74.86 121.33,74.91 121.33,74.92 121.35,74.98 121.35,75.04 121.14,75.28 120.85,75.15 120.83,75.1 120.81,75.05 120.79,75 120.67,75 120.65,75.05 120.65,75.06 120.42,75.28 120.14,75.13 120.11,75.08 120.04,75.13 120.04,75.14 119.96,75.23 119.86,75.28 119.76,75.29 119.66,75.26 119.65,75.26 119.16,75.75 118.94,75.75 118.89,75.81 118.89,76.12 118.95,76.17 119.01,76.23 119.09,76.27 119.17,76.23 119.63,76.16 119.72,76.61 119.7,76.69 119.76,76.76 119.84,76.82 119.89,76.91 119.9,76.95 120.09,76.95
GND on BOTTOM (solid shape): outline of 155 points within 102.9,64.31 107.37,72.83
GND on BOTTOM (solid shape): outline of 370 points within 1.45,23.35 17.97,48.86
GND on BOTTOM (solid shape): outline of 677 points within 1.45,78.6 147.08,102.2
GND on BOTTOM (solid shape): outline of 1223 points within 96.85,71.37 105.51,80.12
GND on BOTTOM (solid shape): outline of 4046 points within 1.45,0.25 228.15,115.65
GND on BOTTOM (solid shape): outline of 11620 points within 98.53,57.67 123.02,91.06
GND on IN1 (solid shape): 111.92,98.08 111.92,95.3 111.91,95.24 111.9,95.17 111.82,95.08 108.11,95.08 107.6,95.59 107.6,96.02 108.08,96.5 108.08,97.98 108.26,98.15 111.84,98.15
GND on IN1 (solid shape): 89.75,92.87 89.82,92.85 89.89,92.85 92.01,92.85 92.34,92.52 92.34,89.37 92.16,89.19 89.75,89.19 89.67,89.26 89.67,89.72 89.66,89.84 89.62,89.94 89.62,92.74 89.75,92.87
GND on IN1 (solid shape): outline of 675 points within 1.45,92.31 147.01,102.44
GND on IN1 (solid shape): outline of 772 points within 1.45,23.33 26.4,73.47
GND on IN1 (solid shape): outline of 1546 points within 1.45,34.71 39.25,88.71
GND on IN1 (solid shape): outline of 2183 points within 1.45,0.25 228.15,115.65
GND on IN2 (solid shape): 92.34,92.57 92.34,89.37 92.16,89.19 89.75,89.19 89.62,89.32 89.62,92.74 89.75,92.87 92.03,92.87
GND on IN2 (solid shape): 111.77,98.03 111.77,95.16 111.74,95.13 108.16,95.13 107.6,95.69 107.6,97.52 107.63,97.53 107.73,97.61 107.8,97.71 107.8,97.72 108.24,98.15 111.64,98.15
GND on IN2 (solid shape): 13.95,46.52 13.95,43.98 11.08,41.11 11.08,40.14 11.14,39.93 11.16,39.7 11.16,26.1 11.13,25.82 11.04,25.56 11.04,24.71 10.45,24.11 8.09,24.11 6.87,25.34 5.58,25.34 4.12,23.89 1.45,23.89 1.45,25.6 1.53,25.77 1.7,25.85 9.19,25.85 10.03,25.36 10.65,26.1 10.65,39.7 10.03,40.44 9.19,39.95 2.8,39.95 2.63,40.03 2.55,40.2 2.55,44.6 2.63,44.77 2.8,44.85 11.5,44.85 12.3,44.05 13.05,44.8 13.05,46.62 13.85,46.62
GND on IN2 (solid shape): outline of 2913 points within 1.45,22.54 147.01,102.44
GND on IN2 (solid shape): outline of 3551 points within 1.45,0.25 228.15,115.65
GND on GND (solid shape): 6.49,102.44 8,100.94 9.51,102.44 9.95,102.44 9.95,100.31 5.98,100.31 5.98,102.44
GND on GND (solid shape): 81.14,102.44 82.65,100.94 84.16,102.44 84.65,102.44 84.65,100.36 80.6,100.36 80.6,102.44
GND on VCC: outline of 168 points within 2.22,1.02 227.38,114.88 ; 1 cut-out
GND on GND: outline of 216 points within 1.45,0.25 228.15,115.65
GNDA on TOP (solid shape): outline of 120 points within 0.25,13.47 9.69,23
GNDA on BOTTOM (solid shape): 25.56,75.29 25.56,74.25 25.33,74.02 20.63,74.02 20.33,74.33 20.33,75.4 20.56,75.62 25.23,75.62
GNDA on BOTTOM (solid shape): 26.32,79.08 26.32,78.29 25.89,77.86 24.26,77.86 24.01,78.11 24.01,79.18 24.11,79.28 26.12,79.28
GNDA on BOTTOM (solid shape): outline of 1215 points within 0.25,13.06 32.27,28.1
GNDA on IN1 (solid shape): 26.98,78.98 26.98,77.89 26.75,77.66 24.09,77.66 23.81,77.38 23.81,75.78 24.04,75.55 26.4,75.55 26.68,75.27 26.68,74.08 26.63,74.02 20.63,74.02 20.38,74.28 20.38,75.32 20.73,75.68 22.05,75.68 22.28,75.9 22.28,78.22 23.22,79.16 26.8,79.16
GNDA on IN1 (solid shape): outline of 667 points within 0.25,13.04 19.34,27.52
GNDA on IN2 (solid shape): outline of 257 points within 0.25,13.47 15.65,25.76
GNDA on IN2 (solid shape): outline of 808 points within 12.63,14.89 32.21,28.08
GNDA on VCC: 2.22,12.45 2.22,13.47 1.02,13.47 1.02,15.23 2.22,15.23 2.22,20.52 1.02,20.52 1.02,21.73 2.22,21.73 2.22,22.99 4.88,22.99 5.13,22.74 12.08,22.74 12.08,22.74 13.09,22.74 15.02,24.67 15.02,25.56 17.66,28.2 20.76,28.2 22.13,26.83 22.13,22.51 22.91,21.73 25.84,21.73 25.94,21.62 25.94,20.73 27.49,19.19 27.87,19.19 28.35,18.7 28.35,17.56 29.26,16.65 30.49,16.65 31.28,17.43 31.27,20.68 30.62,21.34 30.13,21.34 29.5,21.34 29.35,21.34 28.15,22.54 27.97,22.72 27.97,23.14 28.08,23.25 31.17,23.25 32.29,22.13 32.29,20.68 32.29,16.37 31.35,15.42 30.97,15.05 30.79,14.87 25.92,14.87 25.31,15.48 25.31,17.01 24.27,18.04 20.37,18.04 19.59,17.26 19.59,16.5 19.23,16.14 16.82,16.14 16.42,15.74 16.42,13.58 15.8,12.96 6.15,12.96 5.64,12.45
GNDA on GND: 1.86,12.45 1.45,12.62 1.45,12.7 0.5,12.7 0.33,12.78 0.25,12.95 0.25,15.75 0.26,15.8 0.27,15.84 0.36,15.95 0.5,15.99 1.3,15.99 1.31,16 1.45,16 1.45,19.75 0.5,19.75 0.33,19.83 0.25,20 0.25,22.25 0.26,22.3 0.27,22.34 0.36,22.45 0.5,22.49 1.3,22.49 1.31,22.5 1.45,22.5 1.45,22.64 1.8,22.99 4.88,22.99 5.13,22.74 12.08,22.74 12.08,22.74 13.09,22.74 15.02,24.67 15.02,25.56 17.66,28.2 20.76,28.2 22.13,26.83 22.13,22.51 22.91,21.73 25.84,21.73 25.94,21.62 25.94,20.73 27.49,19.19 27.87,19.19 28.35,18.7 28.35,17.56 29.26,16.65 30.49,16.65 31.28,17.43 31.27,20.68 30.62,21.34 30.13,21.34 29.5,21.34 29.35,21.34 28.15,22.54 27.97,22.72 27.97,23.14 28.08,23.25 31.17,23.25 32.29,22.13 32.29,20.68 32.29,16.37 31.35,15.42 30.97,15.05 30.79,14.87 25.92,14.87 25.31,15.48 25.31,17.01 24.27,18.04 20.37,18.04 19.59,17.26 19.59,16.5 19.23,16.14 16.82,16.14 16.42,15.74 16.42,13.58 15.8,12.96 6.15,12.96 5.64,12.45
VCC_3.3V on BOTTOM (solid shape): 48.37,47.84 48.37,46.95 48.31,46.89 47.61,46.89 47.61,47.01 47,47.62 46.1,47.62 46.05,47.67 46.05,47.83 46.1,47.88 48.33,47.88
VDD_DDR on BOTTOM (solid shape): 155.04,29.84 155.04,28.34 155.25,28.14 155.98,28.14 156.01,28.11 156.01,27.5 155.04,27.5 154.94,27.4 153.37,27.4 153.37,27.99 154.28,27.99 154.54,28.24 154.54,29.36 154.38,29.51 154.38,30.3 154.43,30.35 154.54,30.35
VIN on BOTTOM (solid shape): 48.08,96.42 48.08,95.22 47.48,94.62 47.48,89.65 47.23,89.39 42.93,89.39 41.82,88.27 40.67,88.27 40.43,88.52 40.43,88.72 40.42,88.73 40.42,89.52 42.32,91.42 42.32,93.56 42.83,94.07 42.83,96.15 42.96,96.27 44.97,96.27 45.25,96.55 47.94,96.55
+CARD_3V3 on BOTTOM (solid shape): 49.23,22.03 49.23,21.09 48.88,20.74 48.04,20.74 47.51,20.2 47.51,17.99 47.15,17.64 45.98,17.64 45.55,18.07 45.55,21.73 45.75,21.93 48.04,21.93 48.23,22.12 49.14,22.12
+CARD_3V3_R on BOTTOM (solid shape): 51.57,21.9 51.57,20.91 50.96,20.3 50.96,16.06 49.94,15.05 48.85,15.05 48.83,15.07 46.39,15.07 46.01,14.69 46.01,13.06 45.83,12.89 44.33,12.89 44.03,13.19 44.03,14.72 45.55,16.24 47.51,16.24 47.81,16.08 48.1,16.24 49.56,16.24 49.82,16.49 49.82,17.12 49.85,17.13 50.07,17.46 49.85,17.79 49.82,17.8 49.82,20.38 49.49,20.71 49.49,22.08 49.59,22.18 51.29,22.18
+HDMI_5V_OUT on TOP (solid shape): 16.35,92.02 16.35,91.48 15.59,90.72 15.32,90.72 14.38,89.77 13.44,89.77 13.16,90.05 13.16,91.22 13.37,91.42 13.37,91.84 13.53,91.84 13.53,91.78 13.54,91.73 13.56,91.68 13.58,91.63 13.61,91.59 13.65,91.55 13.69,91.52 13.74,91.49 13.79,91.47 13.84,91.46 13.89,91.45 13.94,91.46 14,91.47 14.05,91.49 14.09,91.52 14.13,91.55 14.17,91.59 14.2,91.63 14.22,91.68 14.24,91.73 14.25,91.78 14.25,91.84 14.24,91.89 14.22,91.94 14.2,91.99 14.17,92.03 14.13,92.07 14.09,92.1 14.05,92.13 14,92.15 13.94,92.16 13.89,92.17 13.84,92.16 13.79,92.15 13.74,92.13 13.69,92.1 13.65,92.07 13.61,92.03 13.58,91.99 13.56,91.94 13.54,91.89 13.53,91.84 13.37,91.84 13.37,92.06 13.72,92.41 15.96,92.41
+HDMI_5V_OUT on BOTTOM (solid shape): 15.05,95.23 15.1,95.2 15.35,94.95 15.35,94.52 15.35,94.37 15.35,93.89 14.92,93.46 14.64,93.46 14.31,93.79 14.23,93.79 14.22,93.82 13.87,94.09 13.53,93.82 13.52,93.79 13.34,93.79 13.33,93.77 13.11,93.99 12.71,93.99 12.49,94.2 12.49,94.36 12.48,94.37 12.48,95.26 12.73,95.51 14.77,95.51
+HDMI_5V_OUT on IN1 (solid shape): outline of 233 points within 11.72,89.7 17.81,95.36
+INVPWR_B+ on TOP (solid shape): 74.15,101.02 74.15,99.48 74.05,99.37 69.78,99.37 68.69,98.28 66.81,98.28 66.43,98.66 66.43,100.85 66.76,101.18 74,101.18
+INVPWR_B+ on BOTTOM (solid shape): 74.1,101.02 74.1,99.42 74.35,99.17 74.85,99.17 75.39,98.63 75.39,97.95 75.1,97.65 74.5,97.65 74.06,98.09 72.53,98.09 72.29,98.33 72.29,99.75 71.99,100.06 69.98,100.06 69.71,99.78 69.71,98.97 69.55,98.81 68.36,98.81 67.85,98.31 66.78,98.31 66.58,98.51 66.58,98.69 66.5,98.77 66.5,100.97 66.66,101.12 74,101.12
+IOVDD_CODEC on TOP (solid shape): 25.28,30.43 25.28,30 25.15,29.88 24.57,29.88 24.03,29.34 24.03,28.48 23.88,28.33 23.88,28.32 23.82,28.23 23.71,28.25 23.6,28.36 23.6,28.43 23.45,28.58 23.45,30.54 25.18,30.54
+LAN_VDD on TOP (solid shape): 33.94,69.73 33.94,67.24 34.58,66.6 35.59,66.6 35.77,66.43 35.77,65.71 35.64,65.59 32.62,65.59 32.16,66.05 32.16,69.86 32.77,70.47 33.21,70.47
+LAN_VDD on BOTTOM (solid shape): 34.04,70.42 34.05,70.37 34.07,70.32 34.07,70.09 33.97,69.99 33.13,69.99 33.03,69.88 33.03,69.6 32.85,69.43 32.29,69.43 32.16,69.55 32.16,70.47 32.6,70.9 33.56,70.9
+LAN_VDD on BOTTOM (solid shape): 40.47,67.62 40.47,65.69 40.17,65.39 39.22,65.39 39.22,65.39 38.74,65.39 38.31,65.82 38.28,65.85 37.75,65.85 37.35,66.25 37.35,67.45 37.37,67.47 38.06,67.47 38.16,67.37 38.16,67.12 38.46,66.81 39.12,66.81 39.43,67.12 39.43,67.42 39.73,67.73 40.37,67.73
+LAN_VDD on IN1 (solid shape): 33.87,69.76 33.87,67.24 34.68,66.43 37.88,66.43 38.29,66.84 39.02,66.84 39.33,66.53 39.33,65.79 38.74,65.21 34,65.21 32.52,66.68 32.52,70.24 32.72,70.44 33.18,70.44
+LCDVDD on TOP (solid shape): 70.19,90.94 71.97,90.94 72.13,90.78 72.13,89.35 72.27,89.21 72.8,89.21 73.05,88.96 73.08,88.89 73.05,88.82 72.96,88.53 73.13,88.27 73.13,87.42 73.08,87.23 73.13,87.04 73.13,86.32 72.8,85.99 71.64,85.99 71.05,86.57 71.05,86.95 71.07,87.03 71.08,87.1 71.08,87.79 71.07,87.86 71.05,87.95 71.05,88.07 70.4,88.72 68.55,88.72 67.83,89.44 67.83,91.22 68.25,91.65 69.48,91.65
+LCDVDD on BOTTOM (solid shape): 64.47,100.92 64.47,100.74 64.47,100.7 64.46,100.66 64.46,99.77 64.47,99.73 64.47,99.68 64.47,99.55 65.11,98.91 65.11,98.03 64.93,97.85 62.69,97.85 62.29,98.25 62.29,98.58 62.29,98.65 62.29,98.72 62.29,99.58 62.32,99.68 62.33,99.77 62.33,100.66 62.32,100.75 62.29,100.84 62.29,101.05 62.36,101.12 64.27,101.12
+LCDVDD on BOTTOM (solid shape): 70.12,91.47 70.11,91.44 70.1,91.23 70.21,91.05 70.21,90.92 66.82,87.52 64.76,87.52 64.23,86.99 57.37,86.99 57,87.36 57,88.6 57.23,88.83 58.17,88.83 58.38,88.63 58.38,88.04 58.45,87.97 59.94,87.97 60.68,88.71 64.7,88.71 65.36,89.37 65.4,89.4 65.43,89.44 66.09,90.1 66.12,90.09 66.5,90.19 66.59,90.56 66.58,90.59 66.73,90.74 66.73,92.13 67.01,92.41 69.17,92.41
+LCDVDD on IN1 (solid shape): outline of 198 points within 62.06,90.28 70.37,99.47
+RTCVCC on IN1 (solid shape): outline of 224 points within 92.72,80.12 105.04,93.13
+SOC_VCC on TOP (solid shape): 148.44,73.28 151.69,73.28 152.18,72.8 152.18,69.17 151.31,68.31 147.33,68.31 147,67.98 142.25,67.98 141.51,68.71 141.51,71.3 141.18,71.63 140.26,71.63 139.71,71.07 134.3,71.07 134.22,71.15 134.22,73.96 134.55,74.29 147.44,74.29
+SOC_VCC on TOP (solid shape): 111.41,77.9 111.41,77.03 111.18,76.8 110.9,76.8 110.78,76.69 110.78,76.63 110.77,76.63 110.77,76.2 110.62,76.05 110.24,76.05 110.03,76.26 110.03,76.34 110.08,76.39 110.1,76.4 110.24,76.88 109.77,76.68 109.74,76.66 109.7,76.66 109.59,76.66 109.5,76.63 109.38,76.53 109.31,76.4 109.3,76.38 108.97,76.05 108.82,76.05 108.82,76.04 105.24,76.04 104.42,76.87 103.88,76.87 103.67,77.07 103.67,77.86 103.85,78.04 105.7,78.04 106.23,77.5 106.37,77.5 106.38,77.5 106.48,77.48 106.59,77.5 106.6,77.5 107.57,77.5 107.82,77.75 107.82,77.91 108,78.09 111.22,78.09
+SOC_VCC on BOTTOM (solid shape): 125.31,68.79 125.31,66.86 125.05,66.61 124.06,66.61 123.45,67.22 123.45,68.94 123.58,69.07 125.03,69.07
+SOC_VCC on BOTTOM (solid shape): 148.68,74.35 148.68,72.75 148.58,72.65 146.16,72.65 146.14,72.64 146.07,72.64 146.06,72.63 146.06,71.84 148.65,71.84 148.77,71.71 148.77,68.81 148.47,68.51 147.7,68.51 147.25,68.06 142.75,68.06 141.64,69.17 141.64,71.48 141.31,71.81 140.93,71.81 140.93,71.81 140.1,71.81 139.39,71.1 134.65,71.1 134.65,73.84 135.03,74.22 139.65,74.22 140.32,74.9 148.13,74.9
+SOC_VCC on BOTTOM (solid shape): 104.77,77.82 106.15,77.82 106.16,77.78 106.41,77.49 106.77,77.64 106.84,77.69 106.93,77.66 107.16,77.42 107.37,77.42 107.45,77.5 107.57,77.59 107.65,77.71 107.66,77.72 107.98,78.03 108.2,78.03 108.28,77.95 108.38,77.95 108.42,77.91 110.88,77.91 110.95,77.83 110.95,77.5 110.97,77.4 110.97,75.82 110.87,75.72 110.74,75.72 110.45,76.02 110.35,76.02 110.09,76.28 110.05,76.28 110.01,76.33 110.01,76.34 109.47,76.62 109.44,76.02 109.44,75.88 109.39,75.83 109.32,75.76 108.4,75.76 108.15,76 107.98,76 107.77,75.8 107.56,75.8 107.52,75.84 107.47,75.88 107.32,76.03 107.24,76.03 106.86,75.64 106.01,75.64 105.32,76.34 104.68,76.34 104.58,76.44 104.58,76.75 104.71,77.01 104.52,77.22 104.5,77.23 104.43,77.3 104.02,77.3 103.9,77.42 103.9,77.61 104.38,78.1 104.49,78.1
+SOC_VCC on IN1 (solid shape): outline of 2953 points within 104.54,64.93 147.35,78.47
+SOC_VCC on VCC: 136.79,61.47 132.98,65.28 115.33,65.28 111.41,69.2 111.41,69.45 111.28,69.58 111.28,69.78 110.06,71 109.05,71 107.91,72.14 105.5,72.14 105.06,72.58 105.06,72.96 104.55,73.47 104.55,77.42 104.55,77.43 104.55,77.53 104.55,77.53 104.55,77.68 104.73,77.86 106,77.86 106.26,78.11 107.15,78.11 108.11,79.08 108.36,79.08 109.29,78.15 109.38,78.06 110.52,78.06 110.56,78.02 110.81,77.77 111.36,77.22 113.88,77.22 114,77.35 114.66,77.35 114.79,77.22 114.86,77.22 114.99,77.09 121.42,77.09 121.93,77.6 122.61,77.6 123.37,76.84 145.3,76.84 145.3,76.84 147.37,76.84 147.61,76.61 147.61,65.64 147.25,65.28 142.55,65.28 138.74,61.47
+SOC_VNN on TOP (solid shape): 144.66,81.08 144.66,76.67 143.94,75.95 139.1,75.95 138.61,76.43 134.33,76.43 133.59,77.17 133.59,80.48 133.68,80.57 138.08,80.57 138.84,81.33 144.41,81.33
+SOC_VNN on TOP (solid shape): outline of 195 points within 108.59,75.1 114.79,80.42
+SOC_VNN on BOTTOM (solid shape): 147.86,88.97 147.86,83.63 148.75,82.74 148.75,80.94 148.68,80.87 146.06,80.87 146.04,80.85 146.04,80.1 146.06,80.08 148.68,80.08 148.75,80.02 148.75,77.48 147.86,76.59 141.46,76.59 141.42,76.62 133.84,76.62 133.84,80.35 138.59,80.35 139.48,81.24 142.53,81.24 143.35,82.06 143.35,88.53 144.11,89.29 147.54,89.29
+SOC_VNN on BOTTOM (solid shape): 130.22,83.21 130.22,82.19 130.23,82.19 130.23,82.06 130.22,82.06 130.22,80.92 130.23,80.92 130.23,80.79 130.22,80.79 130.22,79.65 130.23,79.65 130.23,79.03 130.13,78.93 129.61,78.93 128.86,79.67 128.86,81.05 128.86,81.06 128.89,81.18 128.86,81.31 128.86,81.32 128.86,83.14 128.98,83.26 130.17,83.26
+SOC_VNN on BOTTOM (solid shape): outline of 116 points within 107.52,74.89 113.38,80.36
+SOC_VNN on IN1 (solid shape): outline of 5066 points within 108.64,75 147.35,91.9
+SOC_VNN on VCC: 123.58,77.35 122.82,78.11 121.72,78.11 121.21,77.6 114.99,77.6 114.88,77.49 114.77,77.6 113.9,77.6 113.77,77.48 111.46,77.48 110.99,77.95 110.74,78.2 110.63,78.32 109.48,78.32 108.36,79.43 108.36,86.95 108.67,87.25 109.94,87.25 110.45,87.76 118.35,87.76 119.11,87 119.72,87 120.23,87.51 121.12,87.51 121.36,87.75 121.47,87.64 123.07,87.64 123.33,87.89 126,87.89 127.01,88.91 129.47,88.91 131.25,87.13 146.36,87.13 147.61,85.88 147.61,77.58 147.37,77.35 144.58,77.35 144.58,77.35
+USB3_VCCA on TOP (solid shape): outline of 445 points within 11.92,35.04 23.9,56.77
+USB3_VCCA on BOTTOM (solid shape): 24.98,38.92 24.98,37.3 24.34,36.66 21.17,36.66 20.63,37.19 18.73,37.19 18.09,37.83 18.09,39.58 18.3,39.79 18.8,39.79 19.01,39.58 19.51,39.58 19.51,39.51 20.71,39.51 20.88,39.55 21.01,39.66 21.14,39.79 21.24,39.79 21.25,39.8 21.84,39.8 21.85,39.81 24.09,39.81
+USB_SB on TOP (solid shape): 201.91,55.89 201.91,51.98 201.71,51.77 197.59,51.77 196.58,52.79 196.58,55.63 197.04,56.09 201.71,56.09
+USB_SB on TOP (solid shape): 187.49,53.86 187.49,53.45 187.45,53.42 187.41,53.39 187.24,53.22 186.72,53.22 186.47,52.97 186.47,52.76 186.46,52.65 186.47,52.55 186.47,51.81 186.46,51.7 186.47,51.6 186.47,51.32 186.58,51.2 186.58,50.57 186.37,50.35 184.64,50.35 184.01,50.99 184.01,53.86 184.51,54.36 186.98,54.36
+USB_SB on BOTTOM (solid shape): outline of 502 points within 184.06,46.03 201.56,55.3
APDIN on BOTTOM (solid shape): 44.1,100.92 44.1,98.05 43.85,97.8 43.84,97.8 43.72,97.68 39.36,97.68 39.02,98.03 39.02,100.95 39.23,101.15 43.87,101.15
APDIN1 on BOTTOM (solid shape): 48.17,101.05 48.17,98.56 48.52,98.21 49.26,98.21 49.46,98 49.46,97.85 48.76,97.15 48.15,97.15 48.04,97.04 45.25,97.04 44.86,97.42 44.86,100.97 45.04,101.15 48.06,101.15
B+ on TOP (solid shape): outline of 167 points within 165.87,42.02 185.91,82.91
B+ on BOTTOM (solid shape): 140.74,30.41 140.74,29.07 140.65,28.98 140.65,28.79 140.57,28.71 139.36,28.71 139,28.35 139,27.17 138.59,26.75 137.24,26.75 136.57,27.43 136.57,29.81 136.86,30.1 137.41,30.65 140.5,30.65
B+ on BOTTOM (solid shape): 187.21,44.94 187.21,42.95 187.2,42.86 187.21,42.6 187.17,42.57 186.65,42.57 186.65,42.58 185.72,42.58 185.16,42.02 185.16,37.64 185.34,37.46 185.35,37.46 186.37,36.45 186.37,35.26 186.09,34.98 181.9,34.98 175.68,41.2 175.68,48.35 176,48.68 183.47,48.68
B+ on BOTTOM (solid shape): outline of 241 points within 40.19,75.55 74.12,97.37
B+ on BOTTOM (solid shape): outline of 1029 points within 39.91,46.96 59.95,57.08
B+ on IN1 (solid shape): outline of 780 points within 43.29,51.67 53.86,77.58
B+ on IN1 (solid shape): outline of 2865 points within 55.99,18.49 177.02,53.98
BA+ on TOP (solid shape): 191.87,76.65 192.82,76.65 193.01,76.46 193.01,74.11 192.88,73.99 188.56,73.99 188.25,74.3 188.25,76.75 188.78,77.29 191.23,77.29
BA+ on BOTTOM (solid shape): 190.41,79.07 190.53,78.94 191.55,78.94 191.55,78.43 189.9,78.43 189.77,78.3 189.77,77.8 189.9,77.67 191.55,77.67 191.55,76.84 191.74,76.65 192.82,76.65 193.01,76.46 193.01,73.99 192.76,73.73 187.74,73.73 187.55,73.92 187.55,76.46 187.99,76.91 187.99,77.73 189.01,77.73 189.2,77.92 189.2,79.7 189.45,79.96 190.41,79.96
BATT+ on TOP (solid shape): 197.33,79.76 197.33,77.89 196.6,77.16 195.17,77.16 195.04,77.29 195.04,79.45 195.42,79.83 197.26,79.83
BATT+ on BOTTOM (solid shape): 204.15,85.94 204.15,82.97 203.61,82.43 203.61,81.14 203.36,80.88 198.53,80.88 197.33,79.68 197.33,78.05 196.38,77.1 192.63,77.1 192.57,77.16 192.57,77.67 194.22,77.67 194.34,77.8 194.34,78.3 194.22,78.43 192.57,78.43 192.57,79.64 192.58,79.65 192.58,83.71 194.95,86.09 204,86.09
